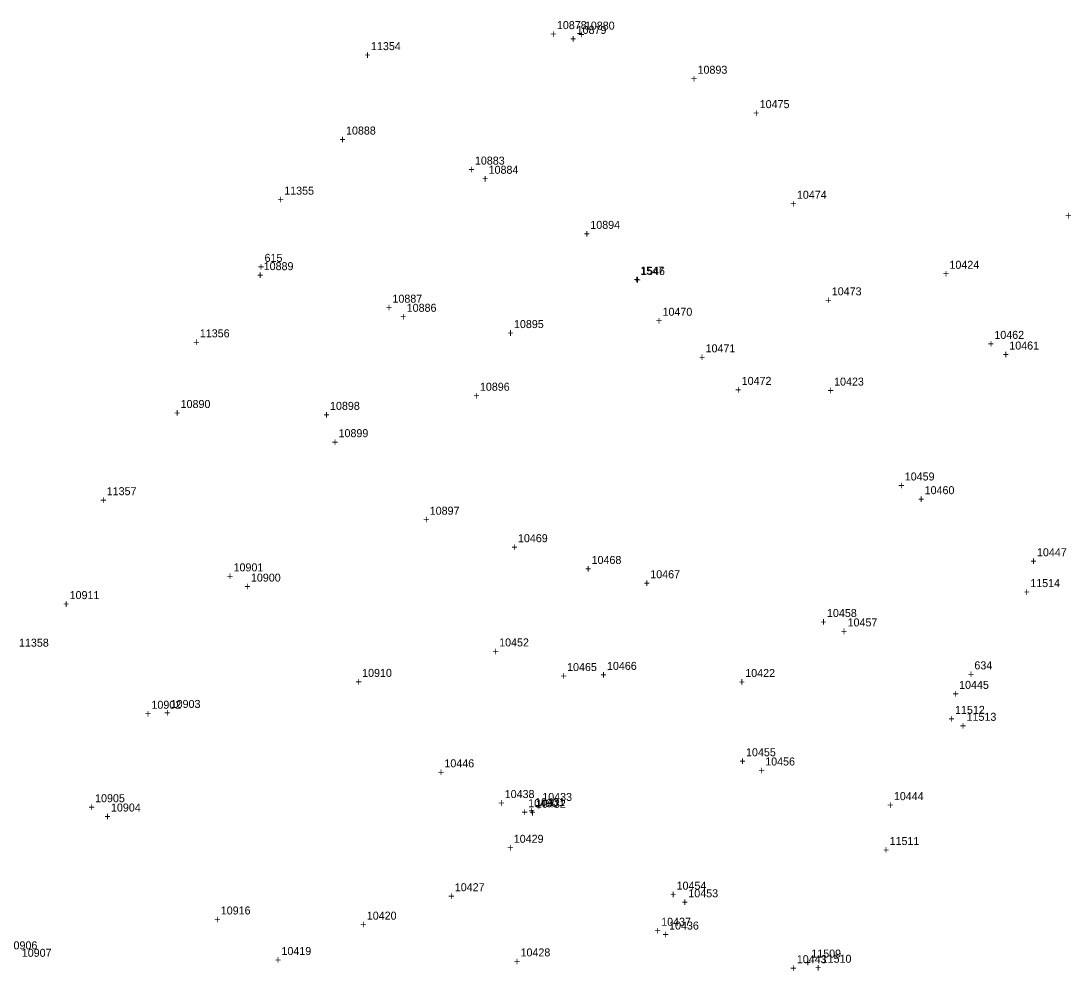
# Model space of a CAD drawing. Extents: x 1160051 to 1162814, y 614604 to 619560.
# Drawn here: x 1161295.2 to 1161623.1, y 617410.8 to 617707.6 of the extents above; entities that cross this region are included whole.
import ezdxf

# ---------------------------------------------------------------- set-up
doc = ezdxf.new("R2010")
doc.units = 0
for name, color, linetype in [('S_Control_Temp_Traverse', 7, 'Continuous'), ('S_Drainage_Culvert_Top', 7, 'Continuous'), ('S_Drainage_Invert', 7, 'Continuous'), ('S_Ground_Elevation', 7, 'Continuous'), ('S_Guardrail_Beam', 7, 'Continuous'), ('S_Trees_TreeLine', 7, 'Continuous')]:
    doc.layers.add(name, color=color, linetype=linetype)

msp = doc.modelspace()

# ---------------------------------------------------------------- texts
at = {"layer": 'S_Control_Temp_Traverse'}
for s, p in [('615', (1161371.23, 617632.32)), ('+', (1161369.17, 617629.57)), ('634', (1161592.89, 617505.05)), ('+', (1161590.83, 617502.3))]:
    msp.add_text(s, height=2.5, dxfattribs=at).set_placement(p)
at = {"layer": 'S_Drainage_Culvert_Top'}
for s, p in [('1547', (1161488.56, 617628.36)), ('+', (1161486.5, 617625.61)), ('10433', (1161457.95, 617463.94)), ('+', (1161455.89, 617461.19))]:
    msp.add_text(s, height=2.5, dxfattribs=at).set_placement(p)
at = {"layer": 'S_Drainage_Invert'}
for s, p in [('1546', (1161488.82, 617628.21)), ('+', (1161486.76, 617625.46)), ('10432', (1161455.98, 617461.8)), ('+', (1161453.92, 617459.05))]:
    msp.add_text(s, height=2.5, dxfattribs=at).set_placement(p)
at = {"layer": 'S_Ground_Elevation'}
for s, p in [('10879', (1161468.69, 617703.54)), ('+', (1161466.63, 617700.79)), ('11354', (1161404.47, 617698.47)), ('+', (1161402.41, 617695.72)), ('10893', (1161506.45, 617691.09)), ('+', (1161504.39, 617688.34)), ('10475', (1161525.85, 617680.35)), ('+', (1161523.79, 617677.6)), ('10884', (1161441.2, 617659.84)), ('+', (1161439.14, 617657.09)), ('11355', (1161377.37, 617653.32)), ('10474', (1161537.47, 617652.04)), ('+', (1161375.31, 617650.57)), ('+', (1161535.41, 617649.29)), ('+', (1161621.28, 617645.55)), ('10894', (1161472.96, 617642.64)), ('+', (1161470.89, 617639.89)), ('10473', (1161548.36, 617621.88)), ('+', (1161546.29, 617619.13)), ('10886', (1161415.62, 617616.74)), ('10470', (1161495.51, 617615.49)), ('+', (1161413.56, 617613.99)), ('10895', (1161449.12, 617611.65)), ('+', (1161493.45, 617612.74)), ('11356', (1161351.02, 617608.76)), ('+', (1161447.05, 617608.9)), ('10462', (1161599.13, 617608.27)), ('+', (1161348.96, 617606.01)), ('+', (1161597.07, 617605.52)), ('10471', (1161508.95, 617604.07)), ('+', (1161506.89, 617601.32)), ('10896', (1161438.48, 617592.07)), ('10472', (1161520.23, 617593.91)), ('+', (1161436.42, 617589.32)), ('+', (1161518.17, 617591.16)), ('10899', (1161394.34, 617577.57)), ('+', (1161392.28, 617574.82)), ('10459', (1161571.16, 617564.04)), ('11357', (1161321.94, 617559.44)), ('+', (1161569.1, 617561.29)), ('+', (1161319.88, 617556.69)), ('10897', (1161422.81, 617553.35)), ('+', (1161420.75, 617550.6)), ('10469', (1161450.36, 617544.76)), ('+', (1161448.29, 617542.01)), ('10468', (1161473.36, 617537.97)), ('10900', (1161366.97, 617532.45)), ('+', (1161471.3, 617535.22)), ('10467', (1161491.68, 617533.51)), ('+', (1161364.91, 617529.7)), ('+', (1161489.62, 617530.76)), ('11514', (1161610.34, 617530.74)), ('+', (1161608.28, 617527.99)), ('10458', (1161546.87, 617521.4)), ('+', (1161544.8, 617518.65)), ('11358', (1161294.55, 617512.13)), ('10452', (1161444.49, 617512.21)), ('+', (1161442.43, 617509.46)), ('10465', (1161465.7, 617504.52)), ('10466', (1161478.16, 617504.87)), ('10910', (1161401.7, 617502.69)), ('+', (1161463.64, 617501.77)), ('+', (1161476.09, 617502.12)), ('+', (1161399.64, 617499.94)), ('+', (1161339.86, 617490.25)), ('10903', (1161341.92, 617493)), ('11512', (1161586.85, 617491.14)), ('+', (1161584.79, 617488.39)), ('11513', (1161590.45, 617488.97)), ('+', (1161588.39, 617486.22)), ('10455', (1161521.58, 617477.9)), ('10446', (1161427.39, 617474.44)), ('+', (1161519.52, 617475.15)), ('+', (1161425.33, 617471.69)), ('10438', (1161446.23, 617464.84)), ('10904', (1161323.27, 617460.63)), ('+', (1161444.17, 617462.09)), ('10430', (1161453.55, 617461.97)), ('10431', (1161455.73, 617462.38)), ('+', (1161321.21, 617457.88)), ('+', (1161451.49, 617459.22)), ('+', (1161453.67, 617459.63)), ('10429', (1161449.05, 617450.87)), ('+', (1161446.99, 617448.12)), ('11511', (1161566.41, 617450.17)), ('+', (1161564.35, 617447.42)), ('10427', (1161430.64, 617435.75)), ('10454', (1161499.9, 617436.23)), ('+', (1161428.58, 617433)), ('+', (1161497.84, 617433.48)), ('10916', (1161357.56, 617428.48)), ('+', (1161355.5, 617425.73)), ('10420', (1161403.16, 617426.86)), ('10437', (1161495.09, 617424.95)), ('+', (1161401.1, 617424.11)), ('+', (1161493.02, 617422.2)), ('10907', (1161295.42, 617415.26)), ('10419', (1161376.51, 617415.81)), ('10428', (1161451.17, 617415.37)), ('11509', (1161541.96, 617415.02)), ('+', (1161374.45, 617413.06)), ('+', (1161449.11, 617412.62)), ('+', (1161539.9, 617412.27)), ('11510', (1161545.21, 617413.4)), ('+', (1161543.15, 617410.65))]:
    msp.add_text(s, height=2.5, dxfattribs=at).set_placement(p)
at = {"layer": 'S_Guardrail_Beam'}
for s, p in [('10878', (1161462.52, 617705.03)), ('+', (1161460.46, 617702.28)), ('10888', (1161396.67, 617672.1)), ('+', (1161394.61, 617669.35)), ('10883', (1161436.92, 617662.71)), ('+', (1161434.86, 617659.96)), ('10889', (1161370.96, 617629.74)), ('+', (1161368.9, 617626.99)), ('10887', (1161411.17, 617619.58)), ('+', (1161409.11, 617616.83)), ('10461', (1161603.8, 617604.94)), ('+', (1161601.74, 617602.19)), ('10890', (1161345.02, 617586.68)), ('10898', (1161391.67, 617586.1)), ('+', (1161342.96, 617583.93)), ('+', (1161389.61, 617583.35)), ('10460', (1161577.36, 617559.76)), ('+', (1161575.29, 617557.01)), ('10447', (1161612.44, 617540.37)), ('+', (1161610.38, 617537.62)), ('+', (1161359.49, 617532.9)), ('10901', (1161361.55, 617535.65)), ('10911', (1161310.36, 617526.99)), ('+', (1161308.3, 617524.24)), ('10457', (1161553.3, 617518.46)), ('+', (1161551.23, 617515.71)), ('10445', (1161588.12, 617498.94)), ('+', (1161586.06, 617496.19)), ('10902', (1161335.91, 617492.74)), ('+', (1161333.85, 617489.99)), ('10456', (1161527.58, 617475.02)), ('+', (1161525.52, 617472.27)), ('10444', (1161567.75, 617464.19)), ('+', (1161316.25, 617460.79)), ('10905', (1161318.31, 617463.54)), ('+', (1161565.69, 617461.44)), ('10453', (1161503.57, 617433.84)), ('+', (1161501.5, 617431.09)), ('10436', (1161497.55, 617423.76)), ('+', (1161495.49, 617421.01)), ('10906', (1161290.98, 617417.58)), ('10443', (1161537.44, 617413.25)), ('+', (1161535.38, 617410.5))]:
    msp.add_text(s, height=2.5, dxfattribs=at).set_placement(p)
at = {"layer": 'S_Trees_TreeLine'}
for s, p in [('10880', (1161471.26, 617704.88)), ('+', (1161469.2, 617702.13)), ('10424', (1161585.11, 617630.17)), ('+', (1161583.04, 617627.42)), ('10423', (1161549.08, 617593.68)), ('+', (1161547.02, 617590.93)), ('10422', (1161521.35, 617502.65)), ('+', (1161519.29, 617499.9))]:
    msp.add_text(s, height=2.5, dxfattribs=at).set_placement(p)

doc.saveas('drawing.dxf')
